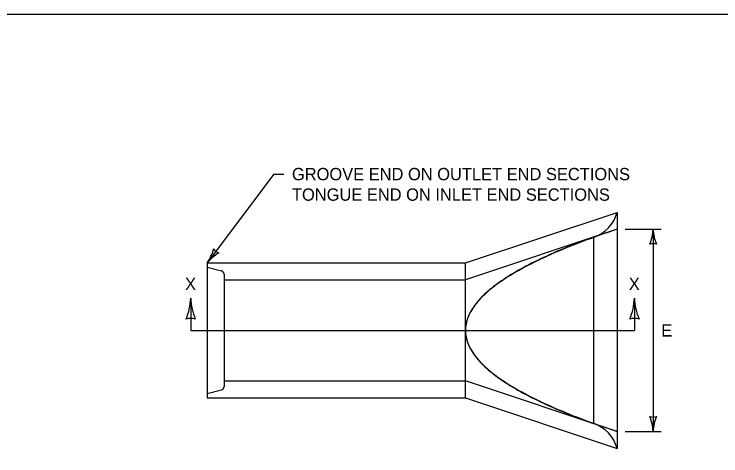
# Model space of a CAD drawing. Extents: x 49991.4 to 50022.1, y 49985 to 50011.4.
# Drawn here: x 50008.666 to 50012.115, y 49996.845 to 49998.999 of the extents above; entities that cross this region are included whole.
import ezdxf

# ---------------------------------------------------------------- set-up
doc = ezdxf.new("R2010")
doc.units = 0
for name, color, linetype in [('Level 1', 7, 'Continuous'), ('Level 2', 7, 'Continuous'), ('Level 3', 7, 'Continuous'), ('Level 4', 7, 'Continuous'), ('Level 6', 7, 'Continuous')]:
    doc.layers.add(name, color=color, linetype=linetype)

msp = doc.modelspace()

# ---------------------------------------------------------------- linework, layer by layer
at = {"layer": 'Level 1'}
for p, q in [((50010.8686, 49997.7858), (50011.6083, 49998.0325)), ((50011.6083, 49998.0325), (50011.6083, 49996.8818)), ((50011.4932, 49997.9121), (50011.4932, 49997.0023)), ((50009.6084, 49997.7858), (50009.6084, 49997.1282)), ((50009.6084, 49997.7858), (50010.8686, 49997.7858)), ((50010.8686, 49997.1282), (50010.8686, 49997.7858)), ((50009.6084, 49997.1282), (50010.8686, 49997.1282)), ((50010.8686, 49997.1282), (50011.6083, 49996.8818))]:
    msp.add_line(p, q, dxfattribs=at)
msp.add_lwpolyline([(49999.3835, 49998.9992), (50016.7501, 49998.9992), (50016.7501, 49987.7988), (49999.3835, 49987.7988)], close=True, dxfattribs=at)
for centre, start, end in [((50011.4431, 49998.0752), 287.0832, 345.4927), ((50011.4431, 49996.8391), 14.5073, 72.9168)]:
    msp.add_arc(centre, 0.1706, start, end, dxfattribs=at)
for points in [[(50011.6083, 49997.9502), (50010.1288, 49997.457), (50011.6083, 49996.964)], [(50011.4932, 49997.9121), (50010.2439, 49997.457), (50011.4932, 49997.0023)]]:
    msp.add_open_spline(points, degree=2, dxfattribs=at)
at = {"layer": 'Level 3'}
for p, q in [((50009.9333, 49998.2192), (50009.6084, 49997.7858)), ((50009.9333, 49998.2192), (50009.982, 49998.2192)), ((50011.6483, 49997.9502), (50011.8241, 49997.9502)), ((50011.7841, 49997.9502), (50011.7841, 49996.964)), ((50011.6483, 49996.964), (50011.8241, 49996.964))]:
    msp.add_line(p, q, dxfattribs=at)
for centre, radius, start, end in [((50011.5709, 49997.959), 0.2134, 337.456, 357.6395), ((50012.0075, 49997.9612), 0.2237, 182.8273, 202.0772), ((50011.7841, 49997.8271), 0.0526, 72.1388, 107.8612), ((50009.4231, 49997.911), 0.2237, 325.9574, 345.2073), ((50009.7737, 49997.6508), 0.2134, 120.5861, 140.7696), ((50009.6823, 49997.8843), 0.0526, 215.2689, 250.9913), ((50009.2318, 49997.6258), 0.2964, 337.456, 357.6395), ((50009.8383, 49997.6289), 0.3107, 182.8273, 202.0772), ((50011.3969, 49997.6258), 0.2964, 337.456, 357.6395), ((50012.0034, 49997.6289), 0.3107, 182.8273, 202.0772), ((50009.528, 49997.4426), 0.073, 72.1388, 107.8612), ((50011.6931, 49997.4426), 0.073, 72.1388, 107.8612), ((50011.7841, 49997.0871), 0.0526, 252.1388, 287.8612), ((50011.5607, 49996.953), 0.2237, 2.8273, 22.0772), ((50011.9973, 49996.9552), 0.2134, 157.456, 177.6395)]:
    msp.add_arc(centre, radius, start, end, dxfattribs=at)
at = {"layer": 'Level 4'}
for p, q in [((50011.6083, 49997.9502), (50010.8686, 49997.7037)), ((50009.6084, 49997.7651), (50009.6782, 49997.7474)), ((50009.6906, 49997.7316), (50009.6906, 49997.1825)), ((50009.6906, 49997.7037), (50010.8686, 49997.7037)), ((50009.6906, 49997.2105), (50010.8686, 49997.2105)), ((50011.6083, 49996.964), (50010.8686, 49997.2105)), ((50009.6084, 49997.149), (50009.6782, 49997.1666))]:
    msp.add_line(p, q, dxfattribs=at)
for centre, start, end in [((50009.6742, 49997.7316), 0, 75.8576), ((50009.6742, 49997.1826), 284.1764, 0)]:
    msp.add_arc(centre, 0.0164, start, end, dxfattribs=at)
at = {"layer": 'Level 6'}
for p, q in [((50009.528, 49997.6136), (50009.528, 49997.457)), ((50011.6931, 49997.6136), (50011.6931, 49997.457)), ((50009.528, 49997.457), (50011.6931, 49997.457))]:
    msp.add_line(p, q, dxfattribs=at)

# ---------------------------------------------------------------- texts
at = {"layer": 'Level 2'}
for s, p in [('GROOVE END ON OUTLET END SECTIONS', (50010.022, 49998.1892)), ('TONGUE END ON INLET END SECTIONS', (50010.022, 49998.0892)), ('X', (50009.5005, 49997.6536)), ('X', (50011.6656, 49997.6536)), ('E', (50011.8241, 49997.4271))]:
    msp.add_text(s, height=0.06, dxfattribs=at).set_placement(p)

doc.saveas('drawing.dxf')
